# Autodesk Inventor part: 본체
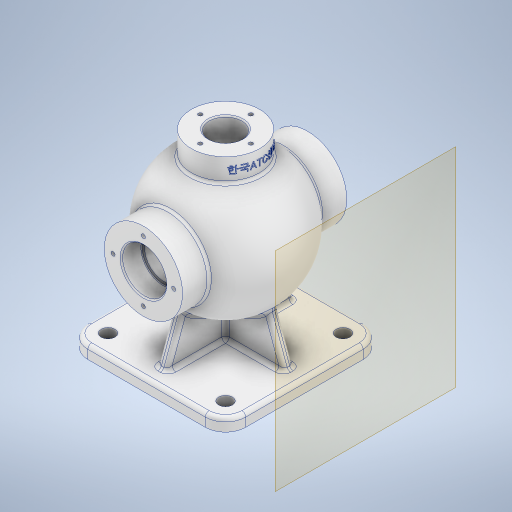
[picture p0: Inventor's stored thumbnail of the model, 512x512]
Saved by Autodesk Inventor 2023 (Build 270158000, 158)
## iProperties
Created: 2023-07
Part Number: 본체
Material: 알루미늄 6061
Document SubType Name: Modeling
Designer: Owner
Density: 2.7 g/cm^3
Appearance: 알루미늄 - 평지
Mass: 1528.71 g
Surface Area: 1177.44 cm^2
Volume: 566.189 cm^3
Author: Owner
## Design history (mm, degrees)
sketch "스케치1"
  geometry: L1 (62.5, 62.5)-(62.5, -62.5); L2 (62.5, -62.5)-(-62.5, -62.5); L3 (-62.5, -62.5)-(-62.5, 62.5); L4 (-62.5, 62.5)-(62.5, 62.5); L5 (62.5, 62.5)-(-62.5, -62.5); L6 (62.5, -62.5)-(-62.5, 62.5); 1 further point
  constraints: 12 end point, 2 midpoint, 2 parallel, 1 perpendicular, 1 vertical
  dimensions: "d0" = 125 distance of L1.end L2.end; "d1" = 125 distance of L2.end L3.end
extrude "돌출1" new body sketch "스케치1" distance "d2" = 10; taper "d3" = 0 deg
fillet "모깎기1" dims "d4" = 16
sketch "스케치3"
  geometry: L1 (85, 65)-(85, -65); L2 (10, 62.5)-(10, -62.5) reference; L3 (10, -62.5)-(0, -62.5) reference; L4 (0, -62.5)-(0, 62.5) reference; L5 (0, 62.5)-(10, 62.5) reference; L6 (85, 65)-(54, 65); L7 (54, -65)-(85, -65); L8 (54, 65)-(54, 44.215); L9 (54, -44.215)-(54, -65); A1 r 54 centre (85, 0) between (54, 44.215) and (54, -44.215); 3 further points
  constraints: 10 end point, 4 perpendicular, 2 midpoint, 2 point on circle, 1 centre point, 1 coincident, 1 collinear, 1 horizontal, 1 horizontal alignment, 1 vertical
  dimensions: "d8" = 130 distance of L1.start L1.end; "d9" = 108 diameter of A1; "d11" = 85 distance of point (0, 0) point (85, 0); "d12" = 31 distance of L1.start L6.end
revolve "회전1" sketch "스케치3" stored, may be unused: angle "d13" = 90 deg
sketch "스케치4"
  geometry: L1 (10, 50.5)-(85, 23.202); L2 (0, 62.5)-(10, 62.5) reference; L3 (85, -23.202)-(10, -50.5); L4 (10, 62.5)-(10, -62.5) reference; L5 (10, -62.5)-(0, -62.5) reference; L6 (0, -62.5)-(0, 62.5) reference; L7 (0, 62.5)-(10, 62.5) reference; L8 (54, 65)-(116, 65) reference; L9 (116, 65)-(116, 44.215) reference; L10 (116, -44.215)-(116, -65) reference; L11 (116, -65)-(54, -65) reference; L12 (54, -65)-(54, -44.215) reference; L13 (54, 44.215)-(54, 65) reference; L14 (85, -23.202)-(85, 23.202); A1 r 54 centre (85, 0) between (116, -44.215) and (116, 44.215) reference; A2 r 54 centre (85, 0) between (54, 44.215) and (54, -44.215) reference; 6 further points
  constraints: 6 end point, 3 midpoint, 2 point on line, 1 coincident
  dimensions: "d14" = 12 vertical distance of point (5, -62.5) L3.end; "d15" = 12 distance of L2.end L1.start; "d16" = 20 deg angle of L5 L3; "d17" = 20 deg angle of L1 L7
extrude "돌출2" join sketch "스케치4" stored distance "d18" = 8; taper "d19" = 0 deg
sketch "스케치6"
  geometry: L1 (4, 50.5)-(4, -50.5) reference; L2 (4, -50.5)-(-4, -50.5) reference; L3 (-4, -50.5)-(-4, 50.5) reference; L4 (-4, 50.5)-(4, 50.5) reference; L5 (-46.5, 62.5)-(46.5, 62.5) reference; L6 (62.5, 46.5)-(62.5, -46.5) reference; L7 (46.5, -62.5)-(-46.5, -62.5) reference; L8 (-62.5, -46.5)-(-62.5, 46.5) reference; C1 r 5.5 at (-46.5, 46.5); C2 r 5.5 at (46.5, 46.5); C3 r 5.5 at (-46.5, -46.5); C4 r 5.5 at (46.5, -46.5); A1 r 16 centre (-46.5, 46.5) between (-46.5, 62.5) and (-62.5, 46.5) reference; A2 r 16 centre (46.5, 46.5) between (62.5, 46.5) and (46.5, 62.5) reference; A3 r 16 centre (46.5, -46.5) between (46.5, -62.5) and (62.5, -46.5) reference; A4 r 16 centre (-46.5, -46.5) between (-62.5, -46.5) and (-46.5, -62.5) reference; 1 further point
  constraints: 4 centre point, 4 coincident
  dimensions: "d30" = 11 diameter of C1; "d31" = 11 diameter of C2; "d32" = 11 diameter of C3; "d33" = 11 diameter of C4
extrude "돌출4" cut sketch "스케치6" extent not by distance; stored distance "d34" = 8; taper "d35" = 0 deg
sketch "스케치7"
  geometry: L1 (54, 65)-(116, 65) reference; L2 (116, 65)-(116, 44.215) reference; L3 (116, -44.215)-(116, -65) reference; L4 (116, -65)-(54, -65) reference; L5 (54, -65)-(54, -44.215) reference; L6 (46.034, -37.385)-(10, -50.5) reference; L7 (10, -50.5)-(10, -62.5) reference; L8 (10, -62.5)-(0, -62.5) reference; L9 (0, -62.5)-(0, 62.5) reference; L10 (0, 62.5)-(10, 62.5) reference; L11 (10, 62.5)-(10, 50.5) reference; L12 (10, 50.5)-(46.034, 37.385) reference; L13 (54, 44.215)-(54, 65) reference; L14 (54, 65)-(116, 65) reference; L15 (85, 65)-(85, -65); L16 (54, -65)-(116, -65) reference; L17 (102.5, 65)-(102.5, 49); L18 (102.5, 49)-(100, 49); L19 (100, 49)-(100, 41.364); L20 (-27.8, 0)-(166.8, 0) reference; L21 (102.5, -49)-(100, -49); L22 (100, -49)-(100, -41.364); L23 (102.5, -49)-(102.5, -65); L24 (102.5, 65)-(85, 65); L25 (102.5, -65)-(85, -65); A1 r 44 centre (85, 0) between (100, -41.364) and (100, 41.364); A2 r 54 centre (85, 0) between (46.034, -37.385) and (54, -44.215) reference; A3 r 54 centre (85, 0) between (54, 44.215) and (46.034, 37.385) reference; A4 r 54 centre (85, 0) between (116, -44.215) and (116, 44.215) reference; 6 further points
  constraints: 18 end point, 3 symmetric about line, 2 midpoint, 2 perpendicular, 2 point on circle, 2 point on line, 2 vertical, 1 centre point, 1 coincident, 1 collinear, 1 parallel
  dimensions: "d37" = 17.5 distance between parallel lines of L15 L17; "d38" = 15 distance between parallel lines of L15 L19; "d39" = 16 distance of L17.start L17.end; "d40" = 44 radius of A1
revolve "회전2" sketch "스케치7" stored, may be unused: angle "d41" = 90 deg
sketch "스케치8"
  geometry: C1 r 17.5 at (0, 0) reference; C2 r 31 at (0, 0) reference; 2 further points
  constraints: 1 vertical alignment
  dimensions: "d42" = 24 distance of C1.centre point (0, 24)
hole "구멍1" sketch "스케치8" at (0, 24) diameter "d43" = 3.242; stored, may be unused: countersink angle "d47" = 90 deg, drill point angle "d49" = 118 deg; dims "d44" = 12, "d45" = 4, "d46" = 2, "d48" = 15
node "작업 평면1"
sketch "스케치13"
  geometry: L1 (46.5, 10)-(-46.5, 10) reference; L2 (-50.5, 10)-(-41.174, 35.622); L3 (-62.5, 0)-(-62.5, 10) reference; 1 further point
  constraints: 2 end point, 1 point on line
  dimensions: "d74" = 12 distance from line of L2.start L3; "d75" = 20 deg angle of L2 L3
feature "리브1" sketch "스케치13" dims "d76" = 1, "d77" = 8, "d78" = 0, "d79" = 0, "d80" = 1, "d81" = 1
fillet "모깎기5" dims "d82" = 3
fillet "모깎기6" dims "d83" = 3
node "작업 평면4"
sketch "스케치14"
  geometry: C1 r 27 at (0, 0); 1 further point
  constraints: 1 centre point, 1 coincident
  dimensions: "d85" = 54 diameter of C1
extrude "돌출7" join sketch "스케치14" stored distance "d86" = 8; taper "d87" = 0 deg
sketch "스케치15"
  geometry: C1 r 13 at (0, 0); 1 further point
  constraints: 1 centre point, 1 coincident
  dimensions: "d88" = 26 diameter of C1
extrude "돌출8" cut sketch "스케치15" stored distance "d89" = 10; taper "d90" = 0 deg
sketch "스케치16"
  geometry: 2 further points
  constraints: 1 horizontal alignment
  dimensions: "d91" = 20 distance of point (0, 0) point (-20, 0)
hole "구멍3" sketch "스케치16" at (-20, 0) diameter "d92" = 3.242; stored, may be unused: countersink angle "d96" = 90 deg, drill point angle "d98" = 118 deg; dims "d93" = 9, "d94" = 4, "d95" = 2, "d97" = 11
fillet "모깎기7" dims "d102" = 3
chamfer "모따기1" distance "d103" = 1; stored, may be unused: second distance "d104" = 2, angle "d105" = 45 deg
fillet "모깎기8" dims "d106" = 0.6
chamfer "모따기2" distance "d107" = 1; stored, may be unused: second distance "d108" = 2, angle "d109" = 45 deg
node "작업 평면5"
sketch "스케치17"
  geometry: L1 (150, 27)-(150, -27) reference; 2 further points
  constraints: 1 horizontal alignment, 1 other
  dimensions: "d111" = 9 distance from line of point (141, 0) L1
feature "엠보싱1" sketch "스케치17" dims "d0" = 125, "d1" = 125, "d8" = 130, "d9" = 108, "d11" = 85, "d12" = 31, "d112" = 0.5, "d113" = 0
feature "ˈ耀ˊ耀ˌ耀ˎ耀ː耀˒耀˔耀˖耀" dims "d0" = 125, "d1" = 125, "d2" = 10, "d3" = 0, "d4" = 16, "d8" = 130, "d9" = 108, "d11" = 85, "d12" = 31, "d13" = 90 deg, "d14" = 12, "d15" = 12, "d16" = 20 deg, "d17" = 20 deg, "d18" = 8, "d19" = 0, "d30" = 11, "d31" = 11, "d32" = 11, "d33" = 11, "d34" = 8, "d35" = 0, "d36" = 88, "d37" = 17.5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
node "솔리드1"
pattern_circular "원형 패턴1" dims angle "d51" = 360 deg
mirror "미러1"
mirror "미러2"
pattern_circular "원형 패턴3" dims angle "d100" = 360 deg
node "절단 모서리 투영1"
node "절단 모서리 투영2"
node "절단 모서리 투영4"
node "절단 모서리 투영5"
node "절단 모서리 투영6"
feature "A9D066F2-1C7D-4E18-AEED-F7BC21143FA4" dims "d43" = 3.242, "d44" = 12, "d45" = 4, "d46" = 2, "d47" = 90 deg, "d48" = 15, "d49" = 118 deg
